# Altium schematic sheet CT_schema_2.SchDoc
size 276 x 169 mm
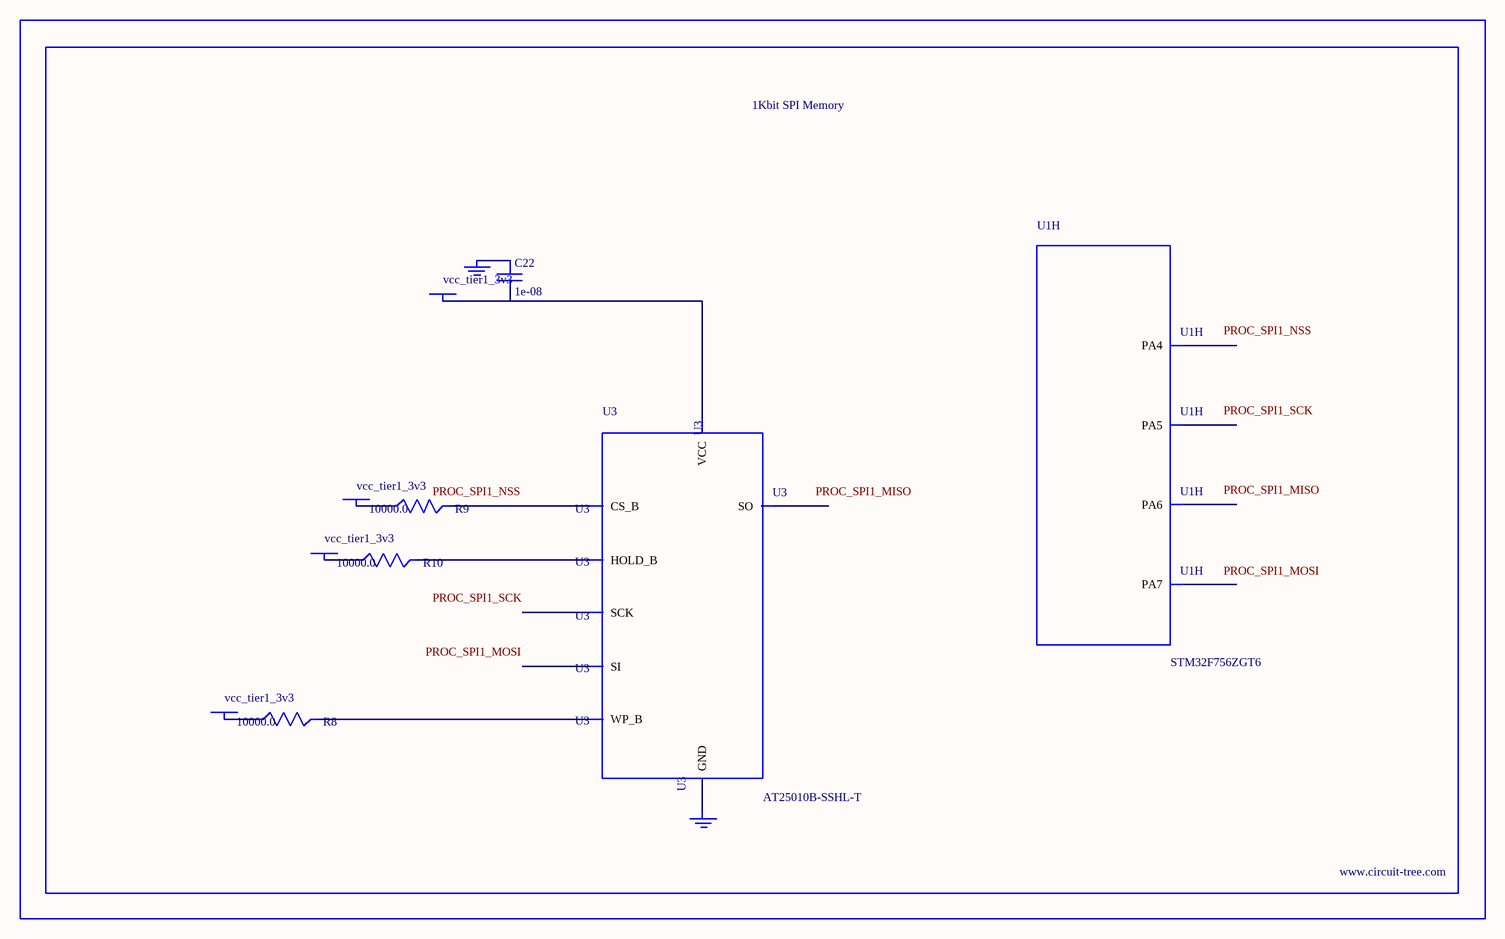
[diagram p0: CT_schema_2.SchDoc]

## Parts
BORDER1  (no value)
C22  1e-08  [C0402]
GND_INSTANCE_1_0  (no value)
GND_INSTANCE_1_1  (no value)
POWER_INSTANCE_1_0  vcc_tier1_3v3
POWER_INSTANCE_1_1  vcc_tier1_3v3
POWER_INSTANCE_1_2  vcc_tier1_3v3
POWER_INSTANCE_1_3  vcc_tier1_3v3
R8  10000.0  [R0603]
R9  10000.0  [R0603]
R10  10000.0  [R0603]
U1  STM32F756ZGT6  [LQFP144]  (part H of 11)
U3  AT25010B-SSHL-T  [SOIC-8]

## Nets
NetC22_1: C22.1 GND_INSTANCE_1_0.0(GND)
NetC22_2: C22.2 POWER_INSTANCE_1_3.0(PWR) U3.8(VCC)
NetGND_INSTANCE_1_1_0: GND_INSTANCE_1_1.0(GND) U3.4(GND)
NetPOWER_INSTANCE_1_0_0: POWER_INSTANCE_1_0.0(PWR) R9.1
NetPOWER_INSTANCE_1_1_0: POWER_INSTANCE_1_1.0(PWR) R8.1
NetPOWER_INSTANCE_1_2_0: POWER_INSTANCE_1_2.0(PWR) R10.1
NetR8_2: R8.2 U3.3(WP_B)
NetR9_2: R9.2 U3.1(CS_B)
NetR10_2: R10.2 U3.7(HOLD_B)

Not connected (* = marked no-connect by the designer): U1 40(PA4) 41(PA5) 42(PA6) 43(PA7); U3 2(SO) 5(SI) 6(SCK)

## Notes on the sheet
- Labels drawn without touching a wire or pin: PROC_SPI1_MISO, PROC_SPI1_MOSI, PROC_SPI1_NSS, PROC_SPI1_SCK

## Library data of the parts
BORDER1 = BORDER_PAGE1
C22 = C0402C103K3RAC
GND_INSTANCE_1_0 GND_INSTANCE_1_1 = GND
POWER_INSTANCE_1_0-POWER_INSTANCE_1_3 = PWR
R8-R10 = RC0603JR-0710KL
